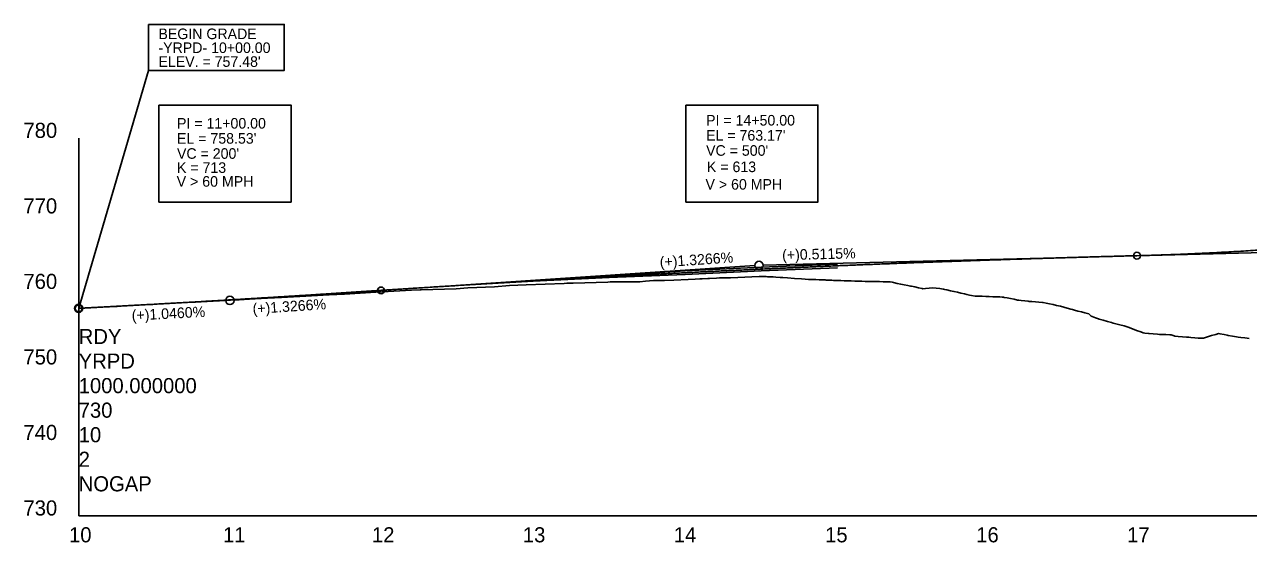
# Model space of a CAD drawing. Extents: x 579185 to 595036, y -53221 to -44640.
# Drawn here: x 579255 to 580065, y -53221 to -52878 of the extents above; entities that cross this region are included whole.
import ezdxf

# ---------------------------------------------------------------- set-up
doc = ezdxf.new("R2010")
doc.units = 0
for name, color, linetype in [('Exist Profile Cell', 7, 'Continuous'), ('Exist Vertical Profile Ground Line', 7, 'Continuous'), ('Exist Vertical Profile Horizontal Axis Label Major', 7, 'Continuous'), ('Exist Vertical Profile Vertical Axis Label', 7, 'Continuous'), ('Prop Grid Mask', 7, 'Continuous'), ('Prop Vertical Profile Curve Label', 7, 'Continuous'), ('Prop Vertical Profile Ditch Grade Median', 7, 'Continuous'), ('Prop Vertical Profile Grade', 7, 'Continuous'), ('Prop Vertical Profile Grade Label', 7, 'Continuous'), ('Prop VPI Label', 7, 'Continuous')]:
    doc.layers.add(name, color=color, linetype=linetype)

msp = doc.modelspace()

# ---------------------------------------------------------------- linework, layer by layer
at = {"layer": 'Exist Profile Cell'}
for q in [(579291.19, -52952.97), (580885.83, -53202.97), (579291.19, -53202.97)]:
    msp.add_line((579291.19, -53202.97), q, dxfattribs=at)
at = {"layer": 'Exist Vertical Profile Ground Line'}
for points in [[(579291.19, -53065.55), (579316.67, -53064.26), (579317.44, -53064.22), (579341.76, -53062.86), (579342.94, -53062.8), (579366.86, -53061.47), (579368.49, -53061.38), (579391.63, -53060.16), (579395.66, -53059.95), (579416.15, -53058.89), (579425.38, -53058.39), (579441.46, -53057.54), (579456.88, -53056.68), (579466.98, -53056.12), (579487.63, -53054.9), (579491.99, -53054.63), (579511.31, -53053.5), (579517.07, -53053.28), (579517.82, -53053.26), (579540.78, -53052.56), (579548.48, -53051.95), (579566.29, -53051.28), (579576.25, -53050.38), (579587.28, -53049.91), (579612.37, -53049.05), (579614.07, -53048.98), (579618.24, -53048.84), (579641.25, -53048.21), (579642.64, -53048.09), (579643.65, -53048.06), (579652.11, -53048.08), (579662.27, -53047.9), (579666.19, -53047.58), (579671.29, -53047.15), (579673.77, -53047.06), (579675.57, -53047.1), (579678.66, -53047.15), (579684.94, -53046.87), (579694.32, -53046.45), (579699.01, -53046.25), (579702.09, -53046.11), (579703.69, -53046), (579707.31, -53045.74), (579708.38, -53045.7), (579713.07, -53045.53), (579714.98, -53045.46), (579717.76, -53045.41), (579721.87, -53045.33), (579722.44, -53045.31), (579727.13, -53045.11), (579731.82, -53044.91), (579736.51, -53044.71), (579741.19, -53044.51), (579741.97, -53044.48), (579745.88, -53044.57), (579746.91, -53044.59), (579750.57, -53044.76), (579752.28, -53044.84), (579755.26, -53045.03), (579755.66, -53045.05), (579756.92, -53045.25), (579759.94, -53045.44), (579764.63, -53045.74), (579769.32, -53046.05), (579771.66, -53046.21), (579774.01, -53046.37), (579776.35, -53046.45), (579778.69, -53046.54), (579781.04, -53046.62), (579783.38, -53046.72), (579785.01, -53046.78), (579785.72, -53046.82), (579788.07, -53046.94), (579789.31, -53047), (579790.41, -53047.03), (579792.76, -53047.11), (579795.1, -53047.19), (579795.4, -53047.2), (579797.44, -53047.27), (579799.79, -53047.36), (579802.13, -53047.45), (579804.62, -53047.56), (579806.82, -53047.6), (579809.16, -53047.65), (579811.51, -53047.69), (579813.85, -53047.73), (579816.19, -53047.78), (579818.54, -53047.83), (579819.33, -53047.85), (579820.06, -53047.87), (579820.88, -53047.89), (579823.22, -53047.95), (579825.57, -53048.01), (579827.91, -53048.08), (579829.37, -53048.14), (579830.26, -53048.36), (579832.6, -53049.01), (579834.94, -53049.64), (579837.29, -53050.04), (579839.63, -53050.44), (579841.49, -53050.77)], [(579841.49, -53050.77), (579841.97, -53050.87), (579844.32, -53051.39), (579846.66, -53051.9), (579849.01, -53052.4), (579849.61, -53052.54), (579851.35, -53052.37), (579853.69, -53052.15), (579856.04, -53051.96), (579858.38, -53052.22), (579860.72, -53052.49), (579863.07, -53052.77), (579863.57, -53052.82), (579863.95, -53052.99), (579865.41, -53053.32), (579867.76, -53053.86), (579870.1, -53054.4), (579872.44, -53054.95), (579874.79, -53055.5), (579877.13, -53056.05), (579878.64, -53056.41), (579879.47, -53056.58), (579880.52, -53056.8), (579881.82, -53057.05), (579884.16, -53057.46), (579886.51, -53057.52), (579888.85, -53057.59), (579891.19, -53057.66), (579893.54, -53057.74), (579895.88, -53057.83), (579898.22, -53057.91), (579900.57, -53058.01), (579902.08, -53058.07), (579902.91, -53058.2), (579903.46, -53058.29), (579905.26, -53058.64), (579907.6, -53059.11), (579909.94, -53059.58), (579912.29, -53060.05), (579913.16, -53060.23), (579914.63, -53060.39), (579916.97, -53060.65), (579919.32, -53060.91), (579919.94, -53060.98), (579921.66, -53061.12), (579924.01, -53061.33), (579926.35, -53061.54), (579928.69, -53061.75), (579929.16, -53061.8), (579931.04, -53062.17), (579933.38, -53062.64), (579935.72, -53063.11), (579938.07, -53063.59), (579940.64, -53064.13), (579942.76, -53064.73), (579945.1, -53065.41), (579947.44, -53066.09), (579948.52, -53066.41), (579949.79, -53066.73), (579952.13, -53067.32), (579954.47, -53067.93), (579956.82, -53068.54), (579959.36, -53069.22), (579960.92, -53070.79), (579961.51, -53071), (579963.85, -53071.84), (579965.78, -53072.55), (579966.19, -53072.66), (579968.95, -53073.43), (579971.7, -53074.21), (579974.46, -53075), (579975.42, -53075.29), (579977.21, -53075.78), (579979.09, -53076.3), (579979.97, -53076.51), (579982.72, -53077.18), (579983.98, -53077.49), (579985.48, -53078.05), (579988.23, -53079.09), (579990.99, -53080.13), (579993.74, -53081.19), (579995.4, -53081.83), (579996.5, -53081.94), (579998.88, -53082.18), (579999.25, -53082.21), (580002.01, -53082.44), (580004.77, -53082.68), (580006.19, -53082.8), (580007.52, -53082.85), (580010.28, -53082.96), (580013.03, -53083.07), (580013.9, -53083.11), (580015.79, -53083.81), (580016.36, -53084.02), (580018.54, -53084.18), (580021.3, -53084.38), (580024.05, -53084.59), (580025.57, -53084.71), (580026.81, -53084.81), (580029.56, -53085.05), (580031.68, -53085.24)], [(580031.68, -53085.24), (580032.32, -53085.25), (580035.14, -53085.27), (580037.83, -53084.46), (580040.58, -53083.63), (580043.34, -53082.8), (580045.23, -53082.24), (580046.09, -53082.41), (580048.85, -53082.97), (580050.86, -53083.38), (580051.6, -53083.5), (580054.36, -53083.94), (580057.11, -53084.39), (580058.17, -53084.56), (580059.87, -53084.79), (580062.62, -53085.16), (580064.04, -53085.36), (580065.38, -53085.54)]]:
    msp.add_lwpolyline(points, dxfattribs=at)
at = {"layer": 'Prop Grid Mask'}
for points in [[(579337.36, -52877.62), (579427.1, -52877.62), (579427.1, -52908.02), (579337.36, -52908.02)], [(579344.29, -52931.02), (579431.65, -52931.02), (579431.65, -52995.2), (579344.29, -52995.2)], [(579692.82, -52931.02), (579780.18, -52931.02), (579780.18, -52995.2), (579692.82, -52995.2)]]:
    msp.add_lwpolyline(points, close=True, dxfattribs=at)
at = {"layer": 'Prop Vertical Profile Curve Label'}
msp.add_line((579291.19, -53065.55), (579337.36, -52908.02), dxfattribs=at)
for centre in [(579991.19, -53030.71), (579991.19, -53030.71), (579491.19, -53053.69), (579491.19, -53053.69), (579291.19, -53065.55)]:
    msp.add_circle(centre, 2.25, dxfattribs=at)
at = {"layer": 'Prop Vertical Profile Ditch Grade Median'}
for points in [[(579291.19, -53065.55), (579341.29, -53062.84), (579391.39, -53059.99), (579441.46, -53056.94), (579491.54, -53053.6), (579541.67, -53050.36), (579591.85, -53047.24), (579642.07, -53043.95), (579692.35, -53040.67), (579742.67, -53038.22), (579793.1, -53036.31)], [(579291.19, -53065.55), (579341.29, -53062.84), (579391.39, -53059.99), (579441.46, -53056.94), (579491.54, -53053.6), (579541.67, -53050.41), (579591.85, -53047.64), (579642.07, -53045.13), (579692.35, -53043.14), (579742.67, -53040.69), (579793.1, -53038.73)]]:
    msp.add_lwpolyline(points, dxfattribs=at)
at = {"layer": 'Prop Vertical Profile Grade'}
for points in [[(579991.19, -53030.71), (579997.59, -53030.54), (580003.99, -53030.34), (580010.39, -53030.13), (580016.79, -53029.89), (580023.19, -53029.63), (580029.59, -53029.35), (580035.99, -53029.05), (580042.39, -53028.73), (580048.79, -53028.39), (580055.19, -53028.03), (580061.59, -53027.64), (580067.99, -53027.24), (580074.39, -53026.81), (580080.79, -53026.36), (580087.19, -53025.9), (580093.59, -53025.41), (580099.99, -53024.9), (580106.39, -53024.37), (580112.79, -53023.81), (580119.19, -53023.24), (580125.59, -53022.65), (580131.99, -53022.03), (580138.39, -53021.4), (580144.79, -53020.74), (580151.19, -53020.06), (580157.59, -53019.36), (580163.99, -53018.64), (580170.39, -53017.9), (580176.79, -53017.14), (580183.19, -53016.36), (580189.59, -53015.55), (580195.99, -53014.73), (580202.39, -53013.88), (580208.79, -53013.02), (580215.19, -53012.13), (580221.59, -53011.22), (580227.99, -53010.29), (580234.39, -53009.34), (580240.79, -53008.37), (580247.19, -53007.37), (580253.59, -53006.36), (580259.99, -53005.33), (580266.39, -53004.27), (580272.79, -53003.19), (580279.19, -53002.09), (580285.59, -53000.98), (580291.99, -52999.84), (580298.39, -52998.68), (580304.79, -52997.49), (580311.19, -52996.29)], [(579491.19, -53053.69), (579501.19, -53053.03), (579511.19, -53052.38), (579521.19, -53051.73), (579531.19, -53051.1), (579541.19, -53050.47), (579551.19, -53049.85), (579561.19, -53049.24), (579571.19, -53048.64), (579581.19, -53048.05), (579591.19, -53047.46), (579601.19, -53046.88), (579611.19, -53046.31), (579621.19, -53045.75), (579631.19, -53045.2), (579641.19, -53044.65), (579651.19, -53044.12), (579661.19, -53043.59), (579671.19, -53043.07), (579681.19, -53042.56), (579691.19, -53042.05), (579701.19, -53041.56), (579711.19, -53041.07), (579721.19, -53040.59), (579731.19, -53040.12), (579741.19, -53039.65), (579751.19, -53039.2), (579761.19, -53038.75), (579771.19, -53038.31), (579781.19, -53037.88), (579791.19, -53037.46), (579801.19, -53037.04), (579811.19, -53036.64), (579821.19, -53036.24), (579831.19, -53035.85), (579841.19, -53035.46), (579851.19, -53035.09), (579861.19, -53034.73), (579871.19, -53034.37), (579881.19, -53034.02), (579891.19, -53033.68), (579901.19, -53033.34), (579911.19, -53033.02), (579921.19, -53032.7), (579931.19, -53032.39), (579941.19, -53032.09), (579951.19, -53031.8), (579961.19, -53031.52), (579971.19, -53031.24), (579981.19, -53030.97), (579991.19, -53030.71)], [(579291.19, -53065.55), (579295.19, -53065.34), (579299.19, -53065.13), (579303.19, -53064.92), (579307.19, -53064.7), (579311.19, -53064.49), (579315.19, -53064.27), (579319.19, -53064.06), (579323.19, -53063.84), (579327.19, -53063.62), (579331.19, -53063.4), (579335.19, -53063.18), (579339.19, -53062.96), (579343.19, -53062.74), (579347.19, -53062.51), (579351.19, -53062.29), (579355.19, -53062.06), (579359.19, -53061.83), (579363.19, -53061.6), (579367.19, -53061.37), (579371.19, -53061.14), (579375.19, -53060.91), (579379.19, -53060.68), (579383.19, -53060.44), (579387.19, -53060.21), (579391.19, -53059.97), (579395.19, -53059.73), (579399.19, -53059.49), (579403.19, -53059.25), (579407.19, -53059.01), (579411.19, -53058.77), (579415.19, -53058.53), (579419.19, -53058.28), (579423.19, -53058.04), (579427.19, -53057.79), (579431.19, -53057.54), (579435.19, -53057.29), (579439.19, -53057.04), (579443.19, -53056.79), (579447.19, -53056.54), (579451.19, -53056.28), (579455.19, -53056.03), (579459.19, -53055.77), (579463.19, -53055.52), (579467.19, -53055.26), (579471.19, -53055), (579475.19, -53054.74), (579479.19, -53054.48), (579483.19, -53054.22), (579487.19, -53053.95), (579491.19, -53053.69)]]:
    msp.add_spline(points, degree=3, dxfattribs=at)
at = {"layer": 'Prop VPI Label'}
for p, q in [((579991.19, -53030.71), (579743.94, -53037.03)), ((579991.19, -53030.71), (580148.44, -53026.69)), ((579491.19, -53053.69), (579738.45, -53037.29)), ((579491.19, -53053.69), (579393.94, -53060.14)), ((579291.19, -53065.55), (579388.45, -53060.46))]:
    msp.add_line(p, q, dxfattribs=at)
for centre in [(579741.19, -53037.11), (579391.19, -53060.32), (579291.19, -53065.55)]:
    msp.add_circle(centre, 2.75, dxfattribs=at)

# ---------------------------------------------------------------- texts
at = {"layer": 'Exist Profile Cell'}
for s, p in [('RDY', (579291.19, -53089.22)), ('YRPD', (579291.19, -53105.47)), ('1000.000000', (579291.19, -53121.72)), ('730', (579291.19, -53137.97)), ('10', (579291.19, -53154.22)), ('2', (579291.19, -53170.47)), ('NOGAP', (579291.19, -53186.72))]:
    msp.add_text(s, height=10, dxfattribs=at).set_placement(p)
at = {"layer": 'Exist Vertical Profile Horizontal Axis Label Major'}
for s, p in [('10', (579284.78, -53220.47)), ('11', (579386.62, -53220.47)), ('12', (579485.16, -53220.47)), ('13', (579585, -53220.47)), ('14', (579684.84, -53220.47)), ('15', (579784.93, -53220.47)), ('16', (579884.88, -53220.47)), ('17', (579984.73, -53220.47))]:
    msp.add_text(s, height=10, dxfattribs=at).set_placement(p)
at = {"layer": 'Exist Vertical Profile Vertical Axis Label'}
for s, p in [('780', (579254.63, -52952.72)), ('770', (579254.63, -53002.72)), ('760', (579254.63, -53052.72)), ('750', (579254.63, -53102.72)), ('740', (579254.63, -53152.72)), ('730', (579254.63, -53202.72))]:
    msp.add_text(s, height=10, dxfattribs=at).set_placement(p)
at = {"layer": 'Prop Vertical Profile Curve Label'}
for s, p in [("VC = 200'", (579356.19, -52966.56)), ("VC = 500'", (579706.19, -52964.54)), ('K = 713', (579356.19, -52975.88)), ('K = 613', (579706.74, -52975.37)), ('V > 60 MPH', (579355.99, -52985.03)), ('V > 60 MPH', (579705.8, -52986.96))]:
    msp.add_text(s, height=7, dxfattribs=at).set_placement(p)
at = {"layer": 'Prop Vertical Profile Grade Label'}
for s, rotation, p in [('(+)0.5115%', 1.46492, (579756.57, -53033.71)), ('(+)1.3266%', 3.79479, (579675.76, -53038.44)), ('(+)1.0460%', 2.99384, (579326.42, -53073.72)), ('(+)1.3266%', 3.79479, (579406.44, -53069.33))]:
    msp.add_text(s, height=7, rotation=rotation, dxfattribs=at).set_placement(p)
at = {"layer": 'Prop VPI Label'}
for s, p in [('BEGIN GRADE', (579343.92, -52887.33)), ('-YRPD- 10+00.00', (579343.92, -52896.51)), ("ELEV. = 757.48'", (579343.92, -52905.69)), ('PI = 11+00.00', (579356.19, -52946.56)), ('PI = 14+50.00', (579706.19, -52944.54)), ("EL = 758.53'", (579356.19, -52956.56)), ("EL = 763.17'", (579706.19, -52954.54))]:
    msp.add_text(s, height=7, dxfattribs=at).set_placement(p)

doc.saveas('drawing.dxf')
